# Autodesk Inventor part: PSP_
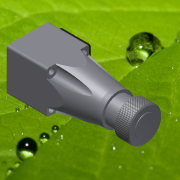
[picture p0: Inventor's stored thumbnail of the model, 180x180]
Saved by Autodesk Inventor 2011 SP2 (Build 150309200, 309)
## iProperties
Created: 2013-12
Part Number: PSP_
Document SubType Name: Modeling
Designer: dorohin
Density: 7.85 g/cm^3
Material: Сталь
Mass: 993.316 g
Surface Area: 204.863 cm^2
Volume: 126.537 cm^3
Author: dorohin
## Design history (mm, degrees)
sketch "Эскиз1"
  geometry: L1 (0, 0)-(0, 30.238); L2 (0, 30.238)-(80, 15); L3 (80, 15)-(85, 15); L4 (85, 15)-(85, 12.5); L5 (85, 12.5)-(97, 12.5); L6 (97, 12.5)-(97, 15); L7 (97, 15)-(98, 16); L8 (98, 16)-(110, 16); L9 (110, 16)-(111, 15); L10 (111, 15)-(111, 10); L11 (111, 10)-(111.5, 10); L12 (111.5, 10)-(111.5, 0); L13 (111.5, 0)-(0, 0); L14 (38, 23)-(38, 0)
  constraints: 28 end point, 3 vertical, 2 parallel, 2 perpendicular, 2 point on line, 1 horizontal
  dimensions: "d2" = 85 distance between parallel lines of L4 L1; "d3" = 111.5 distance between parallel lines of L12 L1; "d4" = 0.5 distance between parallel lines of L10 L12; "d5" = 14 distance between parallel lines of L10 L6; "d6" = 32 diameter of L8 L13; "d7" = 20 diameter of L11 L13; "d8" = 30 diameter of L9.end L13; "d9" = 45 deg angle of L9 L10; "d11" = 45 deg angle of L7 L6 (derived); "d12" = 30 diameter of L6.end L13; "d13" = 25 diameter of L5 L13; "d14" = 30 diameter of L3 L13; "d15" = 5 distance from line of L2.end L4; "d16" = 38 distance between parallel lines of L14 L1; "d17" = 46 diameter of L14.start L13
revolve "Вращение1" sketch "Эскиз1" stored, may be unused: angle "d18" = 90 deg
sketch "Эскиз2"
  geometry: L1 (-20, 20)-(20, 20); L2 (20, 20)-(20, -20); L3 (20, -20)-(-20, -20); L4 (-20, -20)-(-20, 20); C1 r 30.238 at (0, 0) reference; C2 r 10 at (0, 0) reference; 2 further points
  constraints: 8 end point, 2 coincident, 1 vertical, 10 other
  dimensions: "d23" = 40 distance between parallel lines of L2 L4
extrude "Выдавливание1" cut sketch "Эскиз2" distance "d20" = 55; taper "d21" = 0 deg
sketch "Эскиз3"
  geometry: L1 (0, 40)-(0, 0) reference; L2 (0, 0)-(40, 0) reference; L3 (40, 0)-(40, 40) reference; L4 (40, 40)-(0, 40) reference; L5 (0, 40)-(40, 40); L6 (40, 40)-(40, 0); L7 (40, 0)-(0, 0); L8 (0, 0)-(0, 40); 2 further points
  constraints: 8 end point, 1 coincident, 1 vertical, 9 other
  dimensions: "d24" = 40 distance between parallel lines of L6 L8
extrude "Выдавливание2" join sketch "Эскиз3" distance "d25" = 38; taper "d26" = 0 deg
sketch "Эскиз4"
  geometry: L1 (0, 40)-(0, 31.358) reference; L2 (-8.642, 40)-(0, 40) reference; L3 (-40, 31.358)-(-40, 40) reference; L4 (0, 0)-(-8.642, 0) reference; 4 further points
  dimensions: "d27" = 0 horizontal distance of point (-35.5, 35.5) point (-35.5, 4.5); "d28" = 0 horizontal distance of point (-4.5, 35.5) point (-4.5, 4.5); "d29" = 0 vertical distance of point (-4.5, 35.5) point (-35.5, 35.5); "d30" = 0 vertical distance of point (-4.5, 4.5) point (-35.5, 4.5); "d31" = 31 distance of point (-4.5, 4.5) point (-4.5, 35.5); "d32" = 31 distance of point (-4.5, 35.5) point (-35.5, 35.5); "d33" = 4.5 distance from line of L3 point (-35.5, 35.5) (= d34); "d34" = 4.5 distance from line of point (-4.5, 4.5) L1 (derived); "d36" = 4.5 distance from line of point (-4.5, 4.5) L4 (= d37); "d37" = 4.5 distance from line of L2 point (-4.5, 35.5) (derived)
hole "Отверстие1" sketch "Эскиз4" at (-35.5, 35.5), (-35.5, 4.5), (-4.5, 35.5), (-4.5, 4.5) diameter "d38" = 11; stored, may be unused: countersink angle "d42" = 90 deg, drill point angle "d44" = 118 deg; dims "d39" = 6, "d40" = 4, "d41" = 2, "d43" = 50
sketch "Эскиз5"
  geometry: A1 r 5.5 centre (4.5, 35.5) between (0.328, 31.916) and (8.084, 39.672) reference; A2 r 5.5 centre (35.5, 35.5) between (31.916, 39.672) and (39.672, 31.916) reference; A3 r 5.5 centre (35.5, 4.5) between (39.672, 8.084) and (31.916, 0.328) reference; A4 r 5.5 centre (4.5, 4.5) between (8.084, 0.328) and (0.328, 8.084) reference; 5 further points
  constraints: 4 coincident
hole "Отверстие2" sketch "Эскиз5" at (4.5, 35.5), (35.5, 35.5), (35.5, 4.5), (4.5, 4.5) diameter "d45" = 5.5; stored, may be unused: countersink angle "d49" = 90 deg, drill point angle "d51" = 118 deg; dims "d46" = 6, "d47" = 4, "d48" = 2, "d50" = 50
fillet "Сопряжение1" dims "d52" = 2
sketch "Эскиз6"
  geometry: 1 further point
hole "Отверстие3" sketch "Эскиз6" at (20, 18) diameter "d53" = 3; stored, may be unused: countersink angle "d57" = 90 deg, drill point angle "d59" = 118 deg; dims "d54" = 6, "d55" = 4, "d56" = 2, "d58" = 10
sketch "Эскиз7"
  geometry: L1 (0, 36)-(38, 36) reference; L2 (0, 0)-(0, 36) reference; L3 (38, 0)-(0, 0) reference; L4 (38, 29.358)-(38, 36) reference; L5 (4.5, 32.5)-(33.5, 32.5); L6 (33.5, 32.5)-(33.5, 3.5); L7 (33.5, 3.5)-(4.5, 3.5); L8 (4.5, 3.5)-(4.5, 32.5); 2 further points
  constraints: 8 end point, 1 vertical, 9 other
  dimensions: "d60" = 29 distance between parallel lines of L6 L8; "d61" = 4.5 distance between parallel lines of L2 L8 (= d62); "d62" = 4.5 distance between parallel lines of L4 L6 (derived); "d63" = 3.5 distance between parallel lines of L1 L5 (= d64); "d64" = 3.5 distance between parallel lines of L3 L7 (derived)
extrude "Выдавливание3" join sketch "Эскиз7" distance "d65" = 6; taper "d66" = 0 deg
fillet "Сопряжение2" dims "d67" = 2
sketch "Эскиз8"
  geometry: L1 (6.5, 5.5)-(31.5, 30.5); L2 (6.5, 30.5)-(31.5, 5.5); A1 r 2 centre (6.5, 30.5) between (6.5, 32.5) and (4.5, 30.5) reference; A2 r 2 centre (6.5, 5.5) between (4.5, 5.5) and (6.5, 3.5) reference; A3 r 2 centre (31.5, 5.5) between (31.5, 3.5) and (33.5, 5.5) reference; A4 r 2 centre (31.5, 30.5) between (33.5, 30.5) and (31.5, 32.5) reference; 2 further points
  constraints: 4 end point, 1 midpoint, 1 perpendicular
hole "Отверстие4" sketch "Эскиз8" at (19, 18) diameter "d68" = 2.459; stored, may be unused: countersink angle "d72" = 90 deg, drill point angle "d74" = 0 deg; dims "d69" = 6, "d70" = 4, "d71" = 2, "d73" = 6
node "Твердое тело1"
